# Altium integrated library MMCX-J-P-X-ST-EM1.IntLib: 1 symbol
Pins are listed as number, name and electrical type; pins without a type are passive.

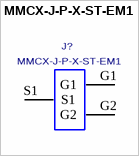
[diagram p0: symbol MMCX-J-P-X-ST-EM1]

## MMCX-J-P-X-ST-EM1
designator J?
MMCX STRAIGHT, EDGE MOUNTING, JACK-50OHM.; MANUFACTURER: SAMTEC
footprint MMCX-J-P-X-ST-EM1
pins: G1, G2, S1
